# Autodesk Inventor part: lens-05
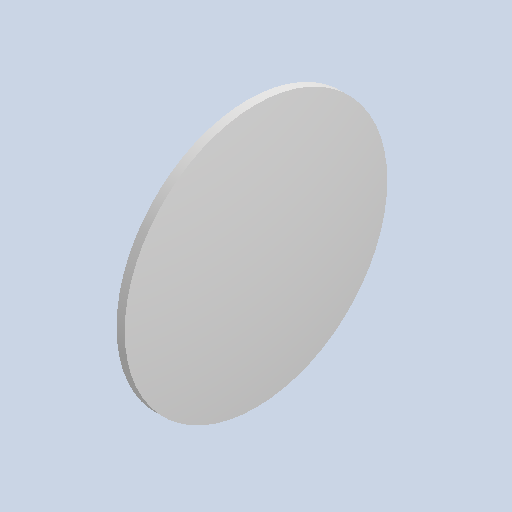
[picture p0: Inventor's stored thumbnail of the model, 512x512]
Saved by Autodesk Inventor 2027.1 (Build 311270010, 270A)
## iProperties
Created: 2026-07
Part Number: lens-05
Material: Generic
Document SubType Name: Modeling
Designer: dunge
Density: 1 g/cm^3
Appearance: Default
Author: dunge
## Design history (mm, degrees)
derived "lens.ipt"
feature "Lens::lens.ipt"
tag "TaggingFeature1"
node "Finishes"
node "Lens"
node "Finish1" dims "Finish1_Area" = 276.91564
other parameters: "SIDE_2_MINOR" = 0.635, "LENS_RADIUS" = 20.32, "SIDE_1_MINOR" = 0.635, "SIDE_1_MAJOR" = 2.54, "SIDE_2_MAJOR" = 1.27
